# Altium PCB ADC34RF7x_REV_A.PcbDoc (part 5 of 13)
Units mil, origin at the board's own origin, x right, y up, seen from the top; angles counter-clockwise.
Board outline 6250 x 2716.54 mil, 18 copper layers (Top Layer, L2 GND, L3 PWR, L4 GND, L5 PWR/SIG, L6 GND, L7 SIGNAL, L8 GND, L9 GND, L10 SIGNAL, L11 GND, L12 SIGNAL, L13 GND, L14 PWR, L15 GND, L16 PWR/SIG, L16 GND, Bottom Layer), stack 95.314 mil thick; 668 components, 786 nets, 3150 pads, 2020 vias.
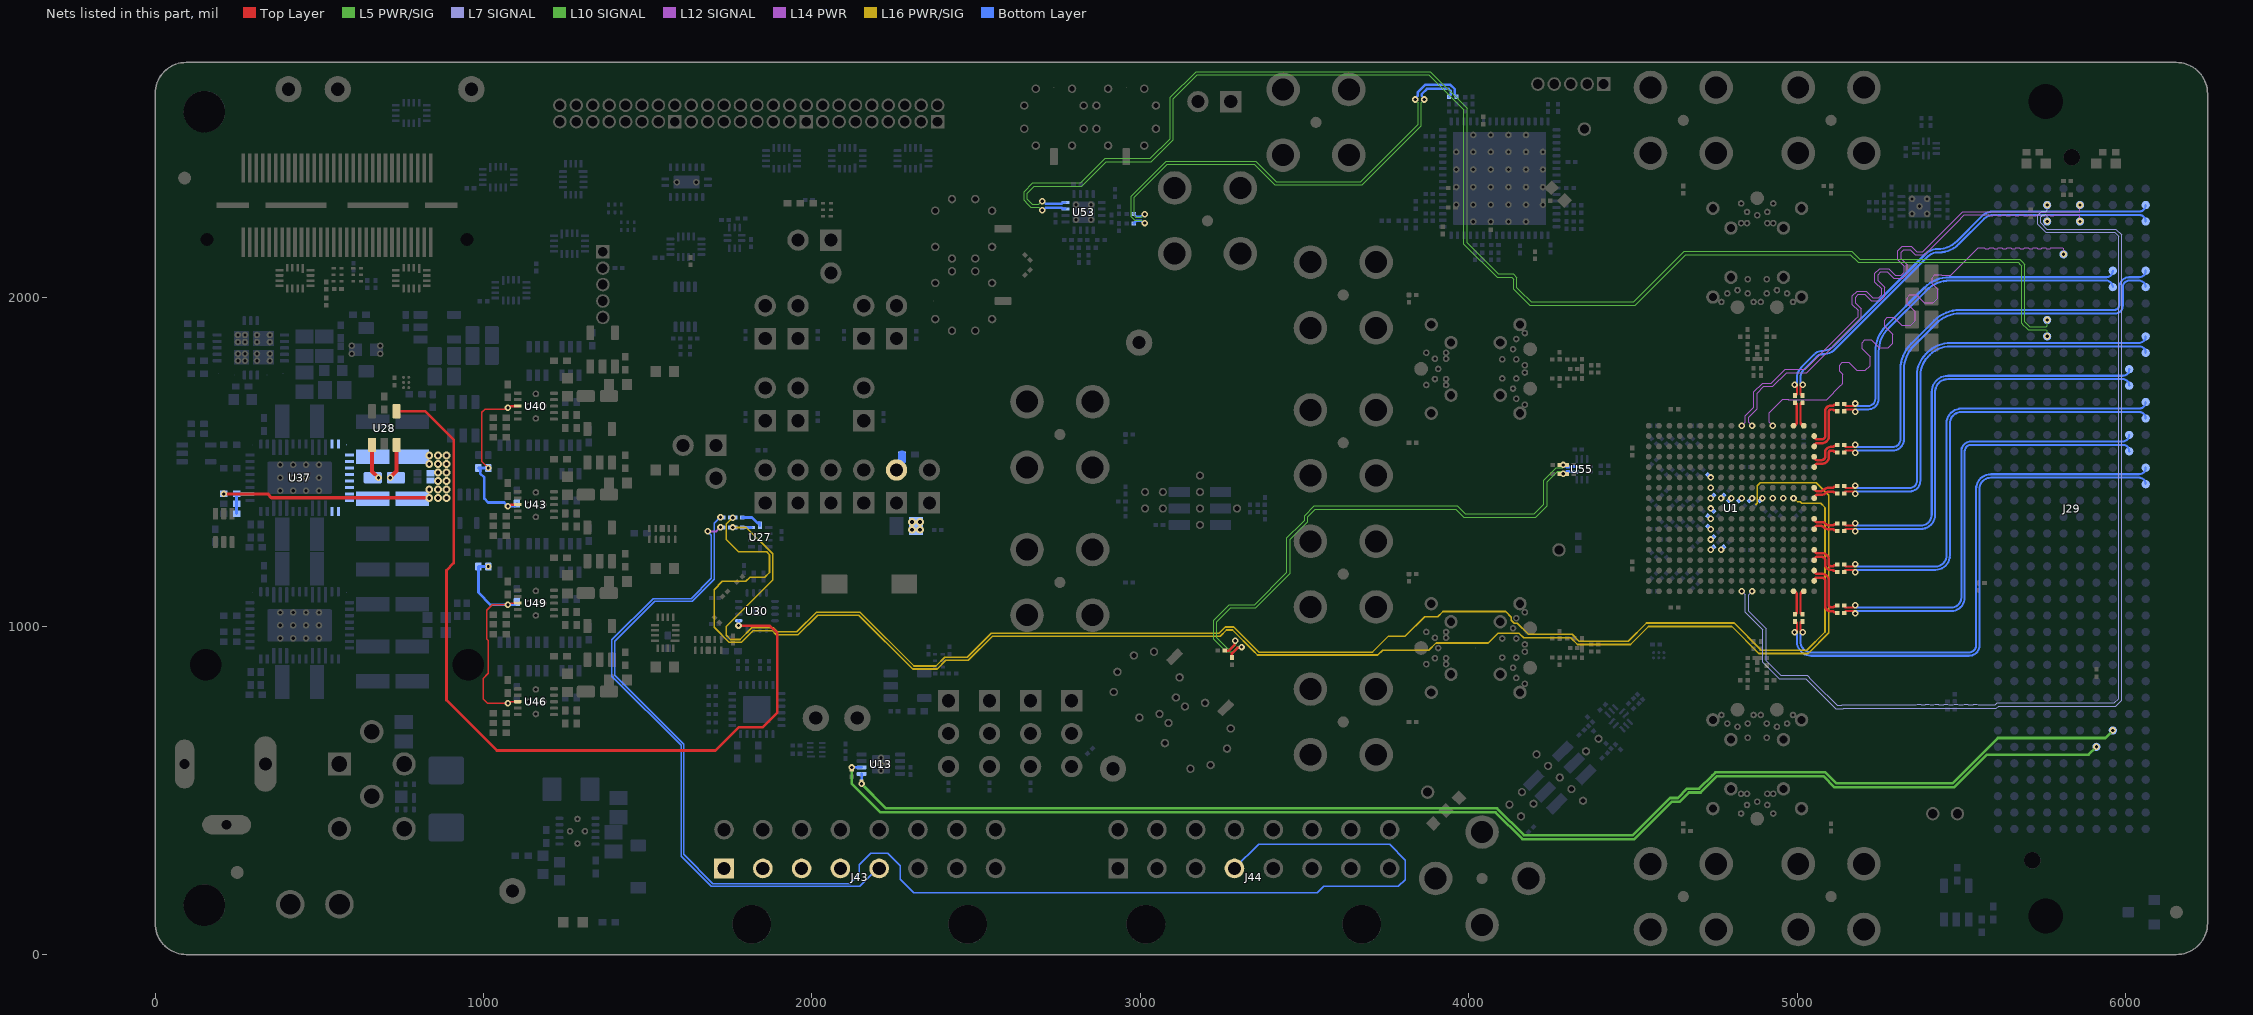
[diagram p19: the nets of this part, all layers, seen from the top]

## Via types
v1: diameter 20, hole 10, Top Layer to Bottom Layer, tented both sides, 1793 vias
v2: diameter 24, hole 12, Top Layer to Bottom Layer, tented both sides, 168 vias
v3: diameter 18, hole 8, Top Layer to Bottom Layer, tented both sides, 59 vias

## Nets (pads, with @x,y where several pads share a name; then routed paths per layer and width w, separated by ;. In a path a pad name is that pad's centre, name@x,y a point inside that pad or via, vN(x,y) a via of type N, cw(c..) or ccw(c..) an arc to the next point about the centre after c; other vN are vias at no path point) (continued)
DCLKB_P: J29.F5 U1.E1 | length 1597.8
  L12 SIGNAL w3.5: v1(4925.98,1610.24) 4915.24,1620.98 4915.24,1649.65 4955.99,1690.41 4959.78,1690.41 4960.12,1690.75 4972.34,1690.75 4973.24,1689.85 5089.85,1689.85 5132.75,1732.75 5135.68,1735.68 5138.99,1738.99 5138.99,1766.33 5129.69,1775.63 5129.69,1794.68 5137.85,1802.85 5156.91,1802.85 5180.94,1778.82 5208.28,1778.82 5222.31,1792.84 5222.31,1820.18 5198.27,1844.22 5198.27,1863.27 5206.44,1871.44 5225.5,1871.44 5249.53,1847.41 5276.87,1847.41 5290.9,1861.43 5290.9,1888.77 5266.86,1912.8 5266.86,1931.86 5275.03,1940.03 5294.09,1940.03 5318.12,1916 5345.46,1916 5359.49,1930.02 5359.49,1957.36 5335.45,1981.39 5335.45,2000.45 5343.62,2008.62 5362.68,2008.62 5386.71,1984.58 5414.05,1984.58 5428.07,1998.61 5428.07,2025.95 5411.52,2042.5 5411.52,2061.56 5419.69,2069.73 5438.75,2069.73 5440.57,2067.91 5467.91,2067.91 5518.51,2118.51 5524.75,2124.75 5552.27,2152.27 5570.45,2152.27 5573.03,2149.69 5583.77,2149.69 5586.35,2152.27 5597.08,2152.27 5599.66,2149.69 5610.4,2149.69 5612.98,2152.27 5623.72,2152.27 5626.3,2149.69 5637.04,2149.69 5639.62,2152.27 5650.36,2152.27 5652.94,2149.69 5663.67,2149.69 5666.25,2152.27 5676.99,2152.27 5679.57,2149.69 5690.31,2149.69 5692.89,2152.27 5703.63,2152.27 5706.21,2149.69 5716.94,2149.69 5719.52,2152.27 5730.26,2152.27 5732.84,2149.69 5743.58,2149.69 5746.16,2152.27 5756.9,2152.27 5759.48,2149.69 5770.22,2149.69 5772.8,2152.27 5809.37,2152.27 5811.42,2150.22 v1(5811.42,2132.27)
DOUT0_ADC_N: C77.1 U1.B17 | length 78.9
  Top Layer w7.4: C77.1@5016.02,1036.3 cw(c5016.02,1041.9) 5010.42,1041.9 5010.42,1096.25 cw(c5020.47,1096.25) U1.B17@5020.47,1106.3
DOUT0_ADC_P: C76.1 U1.C17 | length 78.9
  Top Layer w7.4: U1.C17@4988.98,1106.3 cw(c4988.98,1096.25) 4999.02,1096.25 4999.02,1041.9 cw(c4993.43,1041.9) C76.1@4993.42,1036.3
DOUT0_FMC_N: C77.2 J29.A18 | length 1668.9
  Top Layer w6.3: C77.2@5016.02,1014.25 ccw(c5016.02,1008.1) 5009.87,1008.1 5009.87,988.72 ccw(c5017.22,988.72) v1(5017.22,981.38)
  Bottom Layer w6.3: v1(5017.22,981.38) ccw(c5017.22,974.03) 5009.87,974.03 5009.87,953.05 ccw(c5042.92,953.05) 5042.92,920 5523.82,920 ccw(c5523.82,941.18) 5545,941.18 5545,1417.42 cw(c5590,1417.42) 5590,1462.42 6041.57,1462.42 ccw(c6041.57,1482.27) J29.A18@6061.42,1482.27
DOUT0_FMC_P: C76.2 J29.A19 | length 1685
  Top Layer w6.3: v1(4992.22,981.38) ccw(c4992.22,988.72) 4999.57,988.72 4999.57,1008.1 ccw(c4993.42,1008.1) C76.2@4993.42,1014.25
  Bottom Layer w6.3: v1(4992.22,981.38) cw(c4992.22,974.03) 4999.57,974.03 4999.57,953.05 ccw(c5042.92,953.05) 5042.92,909.7 5523.82,909.7 ccw(c5523.82,941.18) 5555.3,941.18 5555.3,1417.42 cw(c5590,1417.42) 5590,1452.12 6041.57,1452.12 cw(c6041.57,1432.27) J29.A19@6061.42,1432.27
DOUT1_ADC_N: C79.1 U1.A15 | length 168
  Top Layer w7.4: U1.A15@5051.97,1169.29 ccw(c5061.96,1169.29) 5061.96,1159.3 5075.3,1159.3 cw(c5075.3,1137.8) 5096.81,1137.8 5096.81,1062.57 ccw(c5102.52,1062.57) 5102.52,1056.85 5107.76,1056.85 ccw(c5107.76,1061.97) 5111.38,1058.35 cw(c5115,1054.73) 5115,1059.85 5116.13,1059.85 ccw(c5116.13,1067.68) 5121.66,1062.13 C79.1@5121.97,1062.45
DOUT1_ADC_P: C78.1 U1.A16 | length 169.8
  Top Layer w7.4: U1.A16@5051.97,1137.8 cw(c5062.02,1137.8) 5062.02,1147.84 5075.36,1147.84 cw(c5075.36,1137.8) 5085.41,1137.8 5085.41,1062.57 ccw(c5102.52,1062.57) 5102.52,1045.45 5107.76,1045.45 cw(c5107.76,1040.33) 5111.38,1043.95 ccw(c5115,1047.57) 5115,1042.45 5116.13,1042.45 cw(c5116.13,1034.62) 5121.66,1040.16 C78.1@5121.97,1039.85
  Top Layer w12.1: U1.A16@5051.97,1137.8 U1.A16@5053.8,1137.8
DOUT1_FMC_N: C79.2 J29.B16 | length 1370.7
  Top Layer w6.3: C79.2@5144.02,1062.45 ccw(c5150.16,1062.45) 5150.16,1056.3 5169.54,1056.3 ccw(c5169.54,1063.65) v1(5176.89,1063.65)
  Bottom Layer w6.3: v1(5176.89,1063.65) ccw(c5184.24,1063.65) 5184.24,1056.3 5469.51,1056.3 ccw(c5469.51,1086.79) 5500,1086.79 5500,1532.27 cw(c5530.15,1532.27) 5530.15,1562.42 5991.57,1562.42 ccw(c5991.57,1582.27) J29.B16@6011.42,1582.27
DOUT1_FMC_P: C78.2 J29.B17 | length 1370.7
  Top Layer w6.3: C78.2@5144.02,1039.85 cw(c5150.16,1039.85) 5150.16,1046 5169.54,1046 cw(c5169.54,1038.65) v1(5176.89,1038.65)
  Bottom Layer w6.3: v1(5176.89,1038.65) cw(c5184.24,1038.65) 5184.24,1046 5469.51,1046 ccw(c5469.51,1086.79) 5510.3,1086.79 5510.3,1532.27 cw(c5530.15,1532.27) 5530.15,1552.12 5991.57,1552.12 cw(c5991.57,1532.27) J29.B17@6011.42,1532.27
DOUT2_ADC_N: C81.1 U1.A13 | length 105.6
  Top Layer w7.4: U1.A13@5051.97,1232.28 ccw(c5061.96,1232.28) 5061.96,1222.29 5075.3,1222.29 cw(c5075.3,1200.79) 5096.81,1200.79 5096.81,1187.96 ccw(c5102.52,1187.95) 5102.52,1182.24 5107.76,1182.24 ccw(c5107.76,1187.35) 5111.38,1183.73 cw(c5115,1180.11) 5115,1185.23 5116.12,1185.23 ccw(c5116.12,1193.07) 5121.66,1187.52 C81.1@5121.97,1187.83
DOUT2_ADC_P: C80.1 U1.A14 | length 107.5
  Top Layer w7.4: U1.A14@5051.97,1200.79 cw(c5062.02,1200.79) 5062.02,1210.84 5075.36,1210.84 cw(c5075.36,1200.79) 5085.41,1200.79 5085.41,1192.68 5085.4,1187.95 ccw(c5102.52,1187.95) 5102.52,1170.84 5107.76,1170.84 cw(c5107.76,1165.72) 5111.38,1169.34 ccw(c5115,1172.96) 5115,1167.84 5116.12,1167.84 cw(c5116.12,1160.01) 5121.66,1165.55 C80.1@5121.97,1165.24
  Top Layer w12.1: U1.A14@5051.97,1200.79 U1.A14@5053.8,1200.79
DOUT2_FMC_N: C81.2 J29.A14 | length 1387.5
  Top Layer w6.3: C81.2@5144.02,1187.83 ccw(c5150.16,1187.83) 5150.16,1181.69 5169.54,1181.69 ccw(c5169.54,1189.04) v1(5176.89,1189.04)
  Bottom Layer w6.3: v1(5176.89,1189.04) ccw(c5184.24,1189.04) 5184.24,1181.69 5421.69,1181.69 ccw(c5421.69,1215) 5455,1215 5455,1616.82 cw(c5500.59,1616.82) 5500.59,1662.42 6041.57,1662.42 ccw(c6041.57,1682.27) J29.A14@6061.42,1682.27
DOUT2_FMC_P: C80.2 J29.A15 | length 1387.5
  Top Layer w6.3: C80.2@5144.02,1165.24 cw(c5150.16,1165.24) 5150.16,1171.39 5169.54,1171.39 cw(c5169.54,1164.04) v1(5176.89,1164.04)
  Bottom Layer w6.3: v1(5176.89,1164.04) cw(c5184.24,1164.04) 5184.24,1171.39 5421.69,1171.39 ccw(c5421.69,1215) 5465.3,1215 5465.3,1616.82 cw(c5500.59,1616.82) 5500.59,1652.12 6041.57,1652.12 cw(c6041.57,1632.27) J29.A15@6061.42,1632.27
DOUT3_ADC_N: C83.1 U1.A10 | length 79.9
  Top Layer w7.4: U1.A10@5051.97,1326.77 5051.97,1326.72 ccw(c5061.96,1326.72) 5061.96,1316.72 5072.55,1316.72 cw(c5072.55,1294.9) 5087.98,1310.33 5088.03,1310.28 ccw(c5096.63,1318.88) 5096.63,1306.72 5107.76,1306.72 ccw(c5107.76,1311.84) 5111.38,1308.22 cw(c5115,1304.6) 5115,1309.72 5115.69,1309.72 ccw(c5115.69,1318.6) C83.1@5121.97,1312.32
DOUT3_ADC_P: C82.1 U1.A11 | length 79.9
  Top Layer w7.4: U1.A11@5051.97,1295.28 U1.A11@5051.97,1295.28 cw(c5061.96,1295.33) 5061.96,1305.32 5072.49,1305.32 cw(c5072.49,1294.74) 5079.97,1302.22 5080.02,1302.17 ccw(c5096.56,1318.71) 5096.56,1295.32 5107.76,1295.32 cw(c5107.76,1290.2) 5111.38,1293.82 ccw(c5115,1297.44) 5115,1292.32 5115.69,1292.32 cw(c5115.69,1283.45) C82.1@5121.97,1289.73
DOUT3_FMC_N: C83.2 J29.B12 | length 1311.5
  Top Layer w6.3: C83.2@5144.02,1312.32 ccw(c5150.16,1312.32) 5150.16,1306.17 5169.54,1306.17 ccw(c5169.54,1313.52) v1(5176.89,1313.52)
  Bottom Layer w6.3: v1(5176.89,1313.52) ccw(c5184.24,1313.52) 5184.24,1306.17 5376.69,1306.17 ccw(c5376.69,1339.49) 5410,1339.49 5410,1713.23 cw(c5459.18,1713.23) 5459.18,1762.42 5991.57,1762.42 ccw(c5991.57,1782.27) J29.B12@6011.42,1782.27
DOUT3_FMC_P: C82.2 J29.B13 | length 1311.5
  Top Layer w6.3: C82.2@5144.02,1289.73 cw(c5150.16,1289.73) 5150.16,1295.87 5169.54,1295.87 cw(c5169.54,1288.52) v1(5176.89,1288.52)
  Bottom Layer w6.3: v1(5176.89,1288.52) cw(c5184.24,1288.52) 5184.24,1295.87 5376.69,1295.87 ccw(c5376.69,1339.49) 5420.3,1339.49 5420.3,1713.23 cw(c5459.18,1713.23) 5459.18,1752.12 5991.57,1752.12 cw(c5991.57,1732.27) J29.B13@6011.42,1732.27
DOUT4_ADC_N: C85.1 U1.C1 | length 78.9
  Top Layer w7.4: U1.C1@4988.98,1610.24 ccw(c4988.98,1620.28) 4999.02,1620.28 4999.02,1674.64 ccw(c4993.43,1674.64) C85.1@4993.43,1680.24
DOUT4_ADC_P: C84.1 U1.B1 | length 78.9
  Top Layer w7.4: C84.1@5016.02,1680.23 ccw(c5016.02,1674.64) 5010.42,1674.64 5010.42,1620.28 ccw(c5020.47,1620.28) U1.B1@5020.47,1610.24
DOUT4_FMC_N: C85.2 J29.A2 | length 1346.2
  Top Layer w6.3: v1(4992.22,1735.16) cw(c4992.22,1727.81) 4999.57,1727.81 4999.57,1708.43 cw(c4993.43,1708.43) C85.2@4993.43,1702.28
  Bottom Layer w6.3: v1(4992.22,1735.16) ccw(c4992.22,1742.51) 4999.57,1742.51 4999.57,1755.5 cw(c5045.95,1755.5) 5013.16,1788.3 5052.51,1827.65 cw(c5078.02,1802.13) 5078.02,1838.22 ; 5078.07,1838.22 ccw(c5078.07,1882.29) 5109.22,1851.12 ; 5109.23,1851.12 5391.09,2132.98 cw(c5427.87,2096.19) 5427.87,2148.22 ccw(c5427.87,2232.17) 5427.96,2148.22 ccw(c5427.87,2232.17) 5487.23,2172.81 5562.75,2248.32 cw(c5596.79,2214.28) 5596.79,2262.42 6041.57,2262.42 ccw(c6041.57,2282.27) J29.A2@6061.42,2282.27
DOUT4_FMC_P: C84.2 J29.A3 | length 1330.4
  Top Layer w6.3: C84.2@5016.02,1702.28 cw(c5016.02,1708.43) 5009.87,1708.43 5009.87,1727.81 cw(c5017.22,1727.81) v1(5017.22,1735.16)
  Bottom Layer w6.3: v1(5017.22,1735.16) cw(c5017.22,1742.51) 5009.87,1742.51 5009.87,1755.46 cw(c5046.06,1755.46) 5020.47,1781.05 5059.76,1820.33 cw(c5078.07,1802.02) 5078.07,1827.92 5078.16,1827.92 ccw(c5078.16,1882.07) 5116.45,1843.78 5398.31,2125.63 cw(c5427.96,2095.98) 5427.96,2137.92 5432.23,2137.92 ccw(c5432.23,2221.65) 5491.44,2162.44 5570,2241 cw(c5596.83,2214.17) 5596.83,2252.12 6041.57,2252.12 cw(c6041.57,2232.27) J29.A3@6061.42,2232.27
DOUT5_ADC_N: C87.1 U1.A2 | length 169.8
  Top Layer w7.4: U1.A2@5051.97,1578.74 ccw(c5062.02,1578.74) 5062.02,1568.69 5075.36,1568.69 ccw(c5075.36,1578.74) 5085.41,1578.74 5085.41,1653.97 cw(c5102.52,1653.97) 5102.52,1671.09 5107.76,1671.09 ccw(c5107.76,1676.21) 5111.38,1672.59 cw(c5115,1668.97) 5115,1674.09 5116.13,1674.09 ccw(c5116.13,1681.92) 5121.66,1676.37 C87.1@5121.97,1676.69
  Top Layer w12.1: U1.A2@5051.97,1578.74 U1.A2@5053.8,1578.74
DOUT5_ADC_P: C86.1 U1.A3 | length 168
  Top Layer w7.4: U1.A3@5051.97,1547.24 cw(c5061.96,1547.24) 5061.96,1557.24 5075.3,1557.24 ccw(c5075.3,1578.74) 5096.81,1578.74 5096.81,1653.97 cw(c5102.52,1653.97) 5102.52,1659.69 5107.76,1659.69 cw(c5107.76,1654.57) 5111.38,1658.19 ccw(c5115,1661.81) 5115,1656.69 5116.13,1656.69 cw(c5116.13,1648.86) 5121.66,1654.4 C86.1@5121.97,1654.09
DOUT5_FMC_N: C87.2 J29.C6 | length 1107.9
  Top Layer w6.3: C87.2@5144.02,1676.69 ccw(c5150.16,1676.69) 5150.16,1670.54 5169.54,1670.54 ccw(c5169.54,1677.89) v1(5176.89,1677.89)
  Bottom Layer w6.3: v1(5176.89,1677.89) ccw(c5184.24,1677.89) 5184.24,1670.54 5216.79,1670.54 ccw(c5216.79,1691.88) 5238.13,1691.88 5238.13,1835.67 cw(c5348.06,1835.67) 5270.33,1913.4 5388.03,2031.09 cw(c5463.65,1955.47) 5463.65,2062.42 5941.57,2062.42 ccw(c5941.57,2082.27) J29.C6@5961.42,2082.27
DOUT5_FMC_P: C86.2 J29.C7 | length 1107.7
  Top Layer w6.3: C86.2@5144.02,1654.09 cw(c5150.16,1654.09) 5150.16,1660.24 5169.54,1660.24 cw(c5169.54,1652.89) v1(5176.89,1652.89)
  Bottom Layer w6.3: v1(5176.89,1652.89) cw(c5184.24,1652.89) 5184.24,1660.24 5216.79,1660.24 ccw(c5216.79,1691.88) 5248.43,1691.88 5248.43,1835.51 cw(c5348.43,1835.51) 5277.72,1906.22 5394.33,2022.83 cw(c5465.04,1952.12) 5465.04,2052.12 5941.57,2052.12 cw(c5941.57,2032.27) J29.C7@5961.42,2032.27
DOUT6_ADC_N: C89.1 U1.A4 | length 107.5
  Top Layer w7.4: U1.A4@5051.97,1515.75 ccw(c5062.02,1515.75) 5062.02,1505.7 5075.36,1505.7 ccw(c5075.36,1515.75) 5085.41,1515.75 5085.41,1528.58 cw(c5102.52,1528.58) 5102.52,1545.7 5107.76,1545.7 ccw(c5107.76,1550.82) 5111.38,1547.2 cw(c5115,1543.58) 5115,1548.7 5116.13,1548.7 ccw(c5116.13,1556.53) 5121.66,1550.99 C89.1@5121.97,1551.3
  Top Layer w12.1: U1.A4@5051.97,1515.75 U1.A4@5053.8,1515.75
DOUT6_ADC_P: C88.1 U1.A5 | length 105.6
  Top Layer w7.4: U1.A5@5051.97,1484.25 cw(c5061.96,1484.25) 5061.96,1494.25 5075.3,1494.25 ccw(c5075.3,1515.75) 5096.81,1515.75 5096.81,1528.58 cw(c5102.52,1528.58) 5102.52,1534.3 5107.76,1534.3 cw(c5107.76,1529.18) 5111.38,1532.8 ccw(c5115,1536.42) 5115,1531.3 5116.13,1531.3 cw(c5116.13,1523.47) 5121.66,1529.01 C88.1@5121.97,1528.7
DOUT6_FMC_N: C89.2 J29.A6 | length 1339.4
  Top Layer w6.3: C89.2@5144.02,1551.3 ccw(c5150.16,1551.3) 5150.16,1545.15 5169.54,1545.15 ccw(c5169.54,1552.5) v1(5176.89,1552.5)
  Bottom Layer w6.3: v1(5176.89,1552.5) ccw(c5184.24,1552.5) 5184.24,1545.15 5291.41,1545.15 ccw(c5291.41,1568.74) 5315,1568.74 5315,1782.05 cw(c5424.92,1782.05) 5347.2,1859.78 5417.74,1930.32 cw(c5495.47,1852.6) 5495.47,1962.52 5965.21,1962.52 ccw(c5965.21,1978.58) 5981.27,1978.58 5981.27,2032.27 cw(c6011.42,2032.27) 6011.42,2062.42 6041.57,2062.42 ccw(c6041.57,2082.27) J29.A6@6061.42,2082.27
DOUT6_FMC_P: C88.2 J29.A7 | length 1342.9
  Top Layer w6.3: C88.2@5144.02,1528.7 cw(c5150.16,1528.7) 5150.16,1534.85 5169.54,1534.85 cw(c5169.54,1527.5) v1(5176.89,1527.5)
  Top Layer w12.1: v1@5175.69,1528.7 v1(5176.89,1527.5)
  Bottom Layer w6.3: v1(5176.89,1527.5) cw(c5184.24,1527.5) 5184.24,1534.85 5291.41,1534.85 ccw(c5291.41,1568.74) 5325.3,1568.74 5325.3,1781.89 cw(c5425.3,1781.89) 5354.59,1852.6 5424.92,1922.93 cw(c5495.63,1852.22) 5495.63,1952.22 5969.48,1952.22 ccw(c5969.48,1974.31) 5991.57,1974.31 5991.57,2032.27 cw(c6011.42,2032.27) 6011.42,2052.12 6041.57,2052.12 cw(c6041.57,2032.27) J29.A7@6061.42,2032.27
DOUT7_ADC_N: C91.1 U1.A7 | length 79.9
  Top Layer w7.4: U1.A7@5051.97,1421.26 5051.97,1421.21 ccw(c5061.96,1421.21) 5061.96,1411.21 5072.49,1411.21 ccw(c5072.49,1421.8) 5079.97,1414.31 5080.02,1414.36 cw(c5096.56,1397.82) 5096.56,1421.21 5107.76,1421.21 ccw(c5107.76,1426.33) 5111.38,1422.71 cw(c5115,1419.09) 5115,1424.21 5115.69,1424.21 ccw(c5115.69,1433.08) C91.1@5121.97,1426.81
DOUT7_ADC_P: C90.1 U1.A8 | length 79.9
  Top Layer w7.4: U1.A8@5051.97,1389.76 U1.A8@5051.97,1389.76 cw(c5061.96,1389.82) 5061.96,1399.81 5072.55,1399.81 ccw(c5072.55,1421.63) 5087.98,1406.2 5088.03,1406.25 cw(c5096.63,1397.65) 5096.63,1409.81 5107.76,1409.81 cw(c5107.76,1404.69) 5111.38,1408.31 ccw(c5115,1411.93) 5115,1406.81 5115.69,1406.81 cw(c5115.69,1397.94) C90.1@5121.97,1404.21
DOUT7_FMC_N: C91.2 J29.A10 | length 1329.1
  Top Layer w6.3: C91.2@5144.02,1426.81 ccw(c5150.16,1426.81) 5150.16,1420.66 5169.54,1420.66 ccw(c5169.54,1428.01) v1(5176.89,1428.01)
  Bottom Layer w6.3: v1(5176.89,1428.01) ccw(c5184.24,1428.01) 5184.24,1420.66 5343.39,1420.66 ccw(c5343.39,1442.27) 5365,1442.27 5365,1763.56 cw(c5456.01,1763.56) 5365,1763.7 cw(c5456.01,1763.56) 5391.66,1827.92 5396.81,1833.07 cw(c5467.67,1762.2) 5467.67,1862.42 6041.57,1862.42 ccw(c6041.57,1882.27) J29.A10@6061.42,1882.27
DOUT7_FMC_P: C90.2 J29.A11 | length 1329.1
  Top Layer w6.3: C90.2@5144.01,1404.21 cw(c5150.16,1404.21) 5150.16,1410.36 5169.54,1410.36 cw(c5169.54,1403.01) v1(5176.89,1403.01)
  Bottom Layer w6.3: v1(5176.89,1403.01) cw(c5184.24,1403.01) 5184.24,1410.36 5343.39,1410.36 ccw(c5343.39,1442.27) 5375.3,1442.27 5375.3,1763.52 cw(c5456.12,1763.52) 5398.97,1820.67 5404.15,1825.85 cw(c5467.67,1762.2) 5467.67,1852.12 6041.57,1852.12 cw(c6041.57,1832.27) J29.A11@6061.42,1832.27
DVDD09: C105.2 C112.2 C113.2 C114.2 C115.2 C116.2 C117.2 C118.2 C120.2 C132.2 C133.2 C154.2 C208.2 C209.2 C213.2 C214.2 NT1.2 NT6.1 NT7.1 R51.2 R103.2 R119.2 U1.C8 U1.D8 U1.E8 U1.F8 U1.G8 U1.H8 U1.J8 U1.K8 U1.K13 U1.L7 U1.L8 U1.L9 U1.L10 U1.L11 U1.L12 U1.L13 U28.3 | length 886.3
  Top Layer w10: v1(209.01,1402.56) 342.71,1402.56 354.27,1390.99 833.61,1390.99 v2(834.85,1389.75)
  Top Layer w12: v1(715.64,1451.77) 715.64,1452.04 735.31,1471.7 U28.3@735.31,1551.77
  L16 PWR/SIG w4: v1(4988.98,1389.76) NT1.2@4997.46,1381.28
  Bottom Layer w8: C117.2@4729.05,1303.23 v1(4737.01,1295.28) ; C116.2@4729.05,1334.72 v1(4737.01,1326.77) ; v1(4737.01,1232.28) C120.2@4744.96,1240.24 ; v1(4737.01,1263.78) C154.2@4744.96,1271.73 ; v1(4737.01,1358.27) C115.2@4744.96,1350.31 ; v1(4737.01,1389.76) C132.2@4744.96,1397.72 ; v1(4768.5,1232.28) C118.2@4776.46,1240.24 ; v1(4768.5,1389.76) C133.2@4776.46,1397.72 ; C114.2@4792.05,1381.81 v1(4800,1389.76) ; C113.2@4823.54,1381.81 v1(4831.5,1389.76) ; C105.2@4855.04,1381.81 v1(4862.99,1389.76) ; C112.2@4886.54,1381.81 v1(4894.49,1389.76)
  other v1: 4925.98,1389.76 4957.48,1389.76 4737.01,1421.26
  other v2: 2304.81,1293.36 2328.81,1293.36 2304.81,1317.36 2328.81,1317.36 860.85,1389.75 886.85,1389.75 834.85,1415.75 860.85,1415.75 886.85,1415.75 860.85,1441.75 886.85,1441.75 860.85,1467.75 886.85,1467.75 834.85,1493.75 860.85,1493.75 886.85,1493.75 834.85,1519.75 860.85,1519.75 886.85,1519.75
DVDD09-FB: R119.1 R120.2 R121.2 U37.40 | length 100
  Bottom Layer w9: R121.2@248.38,1342.56 R120.2@248.38,1372.56 R119.1@248.38,1402.56 U37.40@288.38,1402.56
DVDD09_GND_SENSE: NT8.1 R197.1 R198.1 | length 5046.2
  L16 PWR/SIG w5: v1(1758.78,1330.42) 1739.12,1310.76 1739.12,1263.76 1776.7,1226.18 1862.05,1226.18 1870.83,1217.41 1870.83,1163.41 1856.02,1148.6 1811.27,1148.6 1798.9,1136.23 1727.41,1136.23 1702.31,1111.13 1702.31,996.45 1748.37,950.39 1785.02,950.39 1821.02,986.39 1878.23,986.39 1891.03,973.59 1957.81,973.59 2017.7,1033.47 2142.96,1033.47 2306.98,869.45 2381.39,869.45 2407.88,895.93 2476.47,895.93 2550.07,969.54 3243.59,969.54 3262.41,988.36 3280.65,988.36 3343.8,925.2 3343.8,925.13 3357.02,911.91 3723.47,911.91 3738.35,926.79 3878.69,926.79 3900.69,948.79 4059.15,948.79 4088.15,977.79 4154.04,977.79 4167.33,964.5 4310.79,964.5 4331.22,944.07 4492.79,944.07 4547.34,998.62 4801.57,998.62 4883.65,916.54 5033.57,916.54 5096.47,979.44 5096.47,1398.81 5058.52,1436.76 4888.07,1436.76 4878.99,1427.68 4878.99,1374.26 NT8.1@4874.31,1369.58
  Bottom Layer w5: R197.1@1751.69,1330.41 v1(1758.78,1330.42) R198.1@1765.85,1330.42
DVDD09_I2C_GND_SENSE: R198.2 U27.5 | length 66.8
  Bottom Layer w9: R198.2@1787.91,1330.44 1817.64,1330.44 1834.42,1313.65 1840.73,1313.65 1841.24,1313.15 U27.5@1841.24,1306.83
DVDD09_I2C_SENSE: R170.2 U27.4 | length 27.7
  Bottom Layer w9: R170.2@1787.91,1300.44 U27.4@1815.56,1300.44
DVDD09_I-SNS: U28.4 U30.5 | length 2514.7
  Top Layer w8: U28.4@735.31,1654.13 822.79,1654.13 908.9,1568.03 908.9,1191.68 887.29,1170.07 887.29,774.38 1040.47,621.2 1706.53,621.2 1777.09,691.77 1848.96,691.77 1894.54,737.34 1894.54,978.33 1871.31,1001.56 v1(1776.38,1001.56)
  Bottom Layer w8: v1(1776.38,1001.56) 1776.77,1001.95 1776.77,1016.09 U30.5@1777.16,1016.48
DVDD09_IN: C216.2 C217.2 R103.1 U28.1 U37.13 U37.14 U37.15 U37.16 U37.17 U37.18 U37.19 U37.20 U37.21 U37.22 U37.23 U37.24 U37.25 U37.26 | length 108.1
  Top Layer w12: U28.1@660.5,1551.5 660.5,1471.44 v1(680.17,1451.77) v1@680.17,1451.5
DVDD09_SENSE: NT1.1 R41.1 R170.1 | length 4666.1
  L16 PWR/SIG w5: v1(1758.78,1300.42) 1800.54,1300.42 1880.46,1220.51 1880.46,1140.15 1739.17,998.86 1739.17,972.32 1752.1,959.39 1781.29,959.39 1817.29,995.39 1881.96,995.39 1894.76,982.59 1954.08,982.59 2013.97,1042.47 2146.68,1042.47 2310.71,878.45 2377.66,878.45 2404.15,904.93 2472.74,904.93 2546.34,978.54 3239.86,978.54 3258.68,997.36 3284.37,997.36 3360.82,920.91 3707.24,920.91 3756,969.67 3807,969.67 3866.13,1028.81 3906.05,1028.81 3921.63,1044.38 4112.4,1044.38 4129.61,1027.17 4129.61,1017.87 4138.69,1008.79 4147.99,1008.79 4181.94,974.84 4190.36,974.84 4190.43,974.91 4315.21,974.91 4335.86,954.25 4486.05,954.25 4541.19,1009.39 4808.18,1009.39 4891.28,926.3 5029.2,926.3 5085.12,982.22 5085.12,1360.98 5072.34,1373.77 5014.55,1373.77 5009.87,1378.45 NT1.1@5000.29,1378.45
  Bottom Layer w5: R41.1@1751.69,1300.41 v1(1758.78,1300.42) R170.1@1765.85,1300.42
DVDD09_uFit: J43.1 J43.3 J43.5 J43.7 NT6.2 NT7.2
DVDD09_uFit_GND_SNS: J44.7 R197.2 | length 4333
  Bottom Layer w4: R197.2@1729.64,1330.41 1722.49,1330.41 v1(1721.65,1331.25) 1703.13,1312.74 1703.13,1143.28 1635.92,1076.07 1520.79,1076.07 1399.26,954.54 1399.26,850.24 1609.46,640.04 1609.46,304.61 1698.01,216.06 2114.8,216.06 2144.13,245.38 2144.13,273.71 2178.47,308.06 2230.78,308.06 2268.7,270.13 2268.7,228.92 2310.23,187.39 3538.17,187.39 3558.18,207.39 3786.02,207.39 3807,228.37 3807,287.79 3759.09,335.71 3360.51,335.71 J44.7@3286.8,262
DVDD09_uFit_SNS: J43.9 R41.2 | length 1989.5
  L14 PWR w6: v1(1683.08,1288.71) 1709.1,1288.71 v1(1721.65,1301.25)
  Bottom Layer w4: v1(1683.08,1288.71) 1683.08,1288.26 1694.16,1277.17 1694.16,1145.63 1632.6,1084.07 1517.48,1084.07 1391.26,957.85 1391.26,846.92 1601.46,636.72 1601.46,299.67 1693.07,208.06 2146.29,208.06 2200.23,262 J43.9@2204.91,262 ; v1(1721.65,1301.25) 1722.49,1300.41 R41.2@1729.64,1300.41
DVDDMEM09: C60.2 C180.2 J19.2 U1.L6 | length 65.4
  Bottom Layer w8: C180.2@4729.05,1460.71 v1(4737.01,1452.76)
  Bottom Layer w24: J19.2@2257.76,1475.36 2257.76,1486.45 2274.45,1503.14 C60.2@2274.45,1522.61
EN_VDD_12: R230.2 R231.2 R232.2 U40.3 U43.3 | length 571.9
  Top Layer w5: v3(1014.58,1481.44) 994.57,1501.45 994.57,1650.95 1003.5,1659.88 1065.39,1659.88 1070.31,1664.8 v1(1074.37,1664.8)
  Top Layer w8: v1(1074.37,1364.8) 1077.62,1364.8 1082.62,1369.8 U43.3@1104.37,1369.8 ; v1(1074.37,1664.8) 1077.62,1664.8 1082.62,1669.8 U40.3@1104.37,1669.8
  Bottom Layer w8: v3(1014.58,1481.44) R231.2@984.58,1481.44 989.56,1476.45 989.56,1464.96 1002.37,1452.15 1002.37,1388.29 1014.09,1376.58 1062.6,1376.58 v1(1074.37,1364.8) 1093.09,1364.8 1094,1365.71 1095.97,1365.71 1101.81,1371.56 R230.2@1101.81,1373.53
EN_VDD_18: R234.2 R235.2 R236.2 U46.3 U49.3 | length 742
  Top Layer w5: U46.3@1104.37,769.8 1079.37,769.8 ccw(c1079.37,764.8) v1(1074.37,764.8) 1012.38,764.8 998.83,778.36 998.83,840.6 1014.61,856.38 1014.61,956.23 1010.19,960.65 1010.19,1048.16 1026.84,1064.8 v1(1074.37,1064.8) 1077.62,1064.8 1082.62,1069.8 U49.3@1104.37,1069.8
  Bottom Layer w8: v3(1014.58,1181.44) R235.2@984.58,1181.44 984.58,1102.21 1021.98,1064.8 v1(1074.37,1064.8) 1093.09,1064.8 1094,1065.71 1095.97,1065.71 1101.81,1071.56 R234.2@1101.81,1073.53
EXT_SYSREF_N: R164.1 R189.1 R193.2 U55.7 | length 1674.7
  Top Layer w7.4: R164.1@3279.03,904.42 3278.74,904.71 3278.74,916.82 3295.65,933.73 3305.97,933.73 v1(3308.33,936.09)
  Top Layer w10: R193.2@4277.86,1490.75 v1(4287.86,1490.75) R189.1@4297.86,1490.75
  L10 SIGNAL w3.5: v1(3308.33,936.09) 3303.77,940.65 3300.87,940.65 3296.88,936.66 3281.44,921.21 3262.15,921.21 3226.14,957.22 3223.21,960.15 3223.21,1017.43 3271.55,1065.77 3347.8,1065.77 3446.71,1164.67 3446.71,1268.71 3493,1315 3500.06,1322.06 3500.06,1336.75 3529.32,1366.02 3965.41,1366.02 3981.59,1349.84 3989.66,1341.77 4200.01,1341.77 4221.5,1363.27 4228.88,1370.65 4228.88,1444.28 4266.84,1482.25 4282.91,1482.25 4285.81,1482.24 4287.86,1484.3 v1(4287.86,1490.75)
  Bottom Layer w7.4: v1(4287.86,1490.75) 4291.2,1490.75 4298.5,1483.45 4306.77,1483.45 4308.21,1484.88 4322.75,1484.88 U55.7@4322.99,1485.12
EXT_SYSREF_P: R177.1 R190.1 R194.2 U55.6 | length 1633.2
  Top Layer w7.4: R177.1@3257.57,925.88 3257.86,925.59 3269.98,925.59 3286.88,942.5 3286.88,952.82 v1(3289.24,955.18)
  Top Layer w10: R194.2@4277.86,1463.74 v1(4287.86,1463.74) R190.1@4297.86,1463.74
  L10 SIGNAL w3.5: v1(3289.24,955.18) 3293.8,950.62 3293.8,947.72 3286.88,940.8 3277.3,931.21 3266.29,931.21 3233.21,964.29 3233.21,1013.29 3275.69,1055.77 3351.95,1055.77 3456.71,1160.53 3456.71,1264.57 3497.14,1305 3510.06,1317.92 3510.06,1332.61 3533.47,1356.02 3961.27,1356.02 3974.52,1342.77 3985.52,1331.77 4204.15,1331.77 4231.5,1359.13 4238.88,1366.5 4238.88,1440.14 4270.98,1472.25 4278.77,1472.25 4285.81,1472.24 4287.86,1470.19 v1(4287.86,1463.74)
  Bottom Layer w7.4: v1(4287.86,1463.74) 4291.2,1463.74 4298.5,1471.05 4306.77,1471.05 4308.21,1469.61 4322.75,1469.61 U55.6@4322.99,1469.37
FCLKA_N: J29.G3 U1.H17 | length 3142.1
  L7 SIGNAL w3.5: v1(4831.5,1106.3) 4842.24,1095.55 4842.24,1041.5 4848.1,1035.64 4895.51,988.23 4895.51,890.52 4946.36,839.67 5026.4,839.67 5033.76,832.31 5048.19,817.88 5117.76,748.3 5140.04,748.3 5141.73,750 5606.88,750 5613.35,756.47 5970.62,756.47 5989.02,774.87 5989.02,2191.08 5971.1,2209 5969.34,2209 5969.29,2209.05 5961.01,2209.05 5960.96,2209 5760.87,2209 5742.27,2227.6 5742.27,2246.81 5747.72,2252.27 5757.42,2252.27 5761.42,2248.27 v1(5761.42,2232.27)
FCLKA_P: J29.G2 U1.G17 | length 3140.5
  L7 SIGNAL w3.5: v1(4862.99,1106.3) 4852.24,1095.55 4852.24,1045.64 4905.51,992.38 4905.51,894.66 4950.5,849.67 5030.54,849.67 5043.76,836.45 5055.26,824.95 5121.91,758.3 5135.9,758.3 5137.59,760 5362.91,760 5365.49,762.58 5376.23,762.58 5378.81,760 5389.55,760 5392.13,762.58 5402.87,762.58 5405.45,760 5416.19,760 5418.77,762.58 5429.5,762.58 5432.08,760 5446.14,760 5448.72,762.58 5459.46,762.58 5462.04,760 5476.1,760 5478.68,762.58 5489.42,762.58 5492,760 5506.06,760 5508.64,762.58 5519.38,762.58 5521.96,760 5536.02,760 5538.6,762.58 5549.33,762.58 5551.91,760 5602.73,760 5609.21,766.47 5966.48,766.47 5979.02,779.02 5979.02,2186.94 5966.96,2199 5756.72,2199 5732.27,2223.46 5732.27,2250.96 5743.58,2262.27 5757.42,2262.27 5761.42,2266.27 v1(5761.42,2282.27)
FCLKB_N: J29.E2 U1.H1 | length 1596.6
  L12 SIGNAL w3.5: v1(4831.5,1610.24) 4842.24,1620.98 4842.24,1640.17 4862.47,1660.4 4868.74,1666.67 4868.74,1713.68 4894.91,1739.85 4921.91,1739.85 4964.33,1782.27 5025.13,1782.27 5182.27,1939.41 5185.58,1942.72 5185.58,1961.78 5168.63,1978.73 5168.63,2006.07 5182.66,2020.09 5210,2020.09 5229.82,2000.27 5248.87,2000.27 5257.04,2008.44 5257.04,2027.5 5237.22,2047.32 5237.22,2074.66 5251.24,2088.68 5278.59,2088.68 5298.41,2068.86 5317.46,2068.86 5325.63,2077.03 5325.63,2096.08 5306.74,2114.98 5306.74,2142.32 5320.76,2156.34 5348.1,2156.34 5364.12,2140.32 5383.18,2140.32 5408.71,2165.85 5480,2237.14 5492,2249.14 5505.13,2262.27 5859.37,2262.27 5861.42,2264.32 v1(5861.42,2282.27)
FCLKB_P: J29.E3 U1.G1 | length 1597.1
  L12 SIGNAL w3.5: v1(4862.99,1610.24) 4852.24,1620.98 4852.24,1636.03 4866.61,1650.4 4878.74,1662.53 4878.74,1709.54 4899.05,1729.85 4926.05,1729.85 4968.47,1772.27 5029.27,1772.27 5189.34,1932.34 5195.58,1938.58 5195.58,1965.92 5178.63,1982.87 5178.63,2001.93 5186.8,2010.09 5205.85,2010.09 5225.68,1990.27 5253.02,1990.27 5267.04,2004.3 5267.04,2031.64 5247.22,2051.46 5247.22,2070.52 5255.39,2078.68 5274.44,2078.68 5294.27,2058.86 5321.61,2058.86 5335.63,2072.89 5335.63,2100.23 5316.74,2119.12 5316.74,2138.18 5324.91,2146.34 5343.96,2146.34 5359.98,2130.32 5387.32,2130.32 5415.78,2158.78 5490,2233 5506.63,2249.63 5509.27,2252.27 5581.79,2252.27 5584.37,2249.69 5595.11,2249.69 5597.69,2252.27 5608.42,2252.27 5611,2249.69 5621.74,2249.69 5624.32,2252.27 5635.06,2252.27 5637.64,2249.69 5648.38,2249.69 5650.96,2252.27 5661.7,2252.27 5664.28,2249.69 5675.01,2249.69 5677.59,2252.27 5688.33,2252.27 5690.91,2249.69 5701.65,2249.69 5704.23,2252.27 5714.97,2252.27 5717.55,2249.69 5728.28,2249.69 5730.86,2252.27 5741.6,2252.27 5744.18,2249.69 5754.92,2249.69 5757.5,2252.27 5768.24,2252.27 5770.82,2249.69 5781.56,2249.69 5784.14,2252.27 5859.37,2252.27 5861.42,2250.22 v1(5861.42,2232.27)
FMC_GA0: J29.C34 R212.1 U13.1 | length 4071.2
  Top Layer w8: v1(2151.24,520) R212.1@2151.24,526
  L5 PWR/SIG w8: v1(2151.24,520) 2226.37,444.88 4086.66,444.88 4168.33,363.21 4499.62,363.21 4613.15,476.73 4636.79,476.73 4665.31,505.24 4701.19,505.24 4741.77,545.83 4750.95,555 5085.81,555 5119.57,521.25 5473.1,521.25 5611.13,659.28 5938.43,659.28 v1(5961.42,682.27)
  Bottom Layer w8: v1(2151.24,520) U13.1@2151.24,550
FMC_GA1: J29.D35 R213.1 U13.2 | length 4091.8
  Top Layer w8: R213.1@2121.24,563.69 v1(2121.24,569.69) 2121.89,569.69 v1@2121.89,570.77
  L5 PWR/SIG w8: v1(2121.24,569.69) 2121.24,520.18 2208.55,432.88 4081.69,432.88 4163.36,351.21 4504.59,351.21 4618.12,464.73 4641.76,464.73 4670.28,493.24 4706.16,493.24 4755.92,543 5080.84,543 5114.6,509.25 5478.07,509.25 5577.57,608.74 5887.89,608.74 v1(5911.42,632.27)
  Bottom Layer w8: v1(2121.24,569.69) U13.2@2151.24,569.69
FPGA_SYSREF_LMK_N: C101.2 R181.2 | length 1425.2
  L10 SIGNAL w3.5: v1(3013.3,2227.24) 3011.64,2227.24 3003.14,2235.74 2982.65,2235.74 2972.05,2246.35 2972.05,2309.59 3078.34,2415.89 3351.19,2415.89 3413.3,2353.78 3671.25,2353.78 3845.85,2528.37 3845.85,2593.38 3837.35,2601.88 v1(3837.35,2603.54)
  Bottom Layer w7.4: C101.2@2980.48,2226.22 2981.27,2226.22 2983.87,2228.82 2983.87,2230.21 2988.2,2234.54 3002.67,2234.54 3009.97,2227.24 v1(3013.3,2227.24) ; v1(3837.35,2603.54) 3837.35,2606.88 3844.65,2614.18 3844.65,2625.45 3867.44,2648.24 3944.61,2648.24 3957.59,2635.26 3957.59,2617.85 3962.72,2612.72 R181.2@3962.72,2611.93
FPGA_SYSREF_LMK_P: C100.2 R166.2 | length 1367.6
  L10 SIGNAL w3.5: v1(3013.3,2254.24) 3011.64,2254.24 3003.14,2245.74 2986.79,2245.74 2982.05,2250.49 2982.05,2305.45 3082.48,2405.89 3347.05,2405.89 3406.23,2346.71 3409.16,2343.78 3675.39,2343.78 3855.85,2524.23 3855.85,2593.38 3864.35,2601.88 v1(3864.35,2603.54)
  Bottom Layer w7.4: C100.2@2980.48,2255.27 2981.27,2255.27 2983.87,2252.67 2983.87,2251.28 2988.2,2246.94 3002.67,2246.94 3009.97,2254.24 v1(3013.3,2254.24) ; v1(3864.35,2603.54) 3864.35,2606.88 3857.05,2614.18 3857.05,2620.31 3872.58,2635.84 3939.47,2635.84 3945.19,2630.12 3945.19,2617.85 3940.07,2612.72 R166.2@3940.07,2611.93
FPGA_SYSREF_N: J29.G10 U53.12 | length 4304.1
  L10 SIGNAL w3.5: v1(2701.33,2293.62) 2699.66,2293.62 2691.16,2285.12 2671.28,2285.12 2663.56,2292.85 2656.06,2300.34 2656.06,2318.62 2676.85,2339.41 2817.75,2339.41 2818.25,2339.91 2822.04,2339.91 2896.61,2414.48 3034.03,2414.48 3035.96,2416.41 3036.67,2416.41 3100.89,2480.63 3100.89,2605.73 3173.86,2678.69 3879.04,2678.69 3985.52,2572.21 3985.52,2163 4086.25,2062.27 4130.9,2062.27 4137,2056.16 4137,2025.88 4149,2013.89 4185.73,1977.16 4506.93,1977.16 4660.62,2130.85 5162.56,2130.85 5183,2110.41 5185.93,2107.48 5673.28,2107.48 5679.8,2100.96 5683.94,2096.82 5683.94,2014.64 5683.94,1922.02 5687.81,1918.15 5697.83,1908.13 5703.69,1902.27 5759.37,1902.27 5761.42,1900.22 v1(5761.42,1882.27)
  Bottom Layer w7.4: v1(2701.33,2293.62) 2704.66,2293.62 2711.96,2286.32 2761.46,2286.32 2765.11,2289.97 U53.12@2772.2,2289.97
FPGA_SYSREF_P: J29.G9 U53.11 | length 4337.3
  L10 SIGNAL w3.5: v1(2701.33,2266.62) 2699.66,2266.62 2691.16,2275.12 2667.14,2275.12 2656.49,2285.77 2646.06,2296.2 2646.06,2322.77 2672.7,2349.41 2818.1,2349.41 2892.67,2423.98 3030.1,2423.98 3090.89,2484.77 3090.89,2609.87 3169.71,2688.69 3883.18,2688.69 3995.52,2576.36 3995.52,2167.14 4090.39,2072.27 4135.04,2072.27 4147,2060.3 4147,2030.02 4156.07,2020.96 4189.87,1987.16 4502.79,1987.16 4656.47,2140.85 5166.7,2140.85 5190.07,2117.48 5677.42,2117.48 5686.87,2108.03 5693.94,2100.96 5693.94,2010.5 5693.94,1926.16 5707.83,1912.27 5759.37,1912.27 5761.42,1914.32 v1(5761.42,1932.27)
  Bottom Layer w7.4: v1(2701.33,2266.62) 2704.66,2266.62 2711.96,2273.92 2761.46,2273.92 2765.11,2270.28 U53.11@2772.2,2270.28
